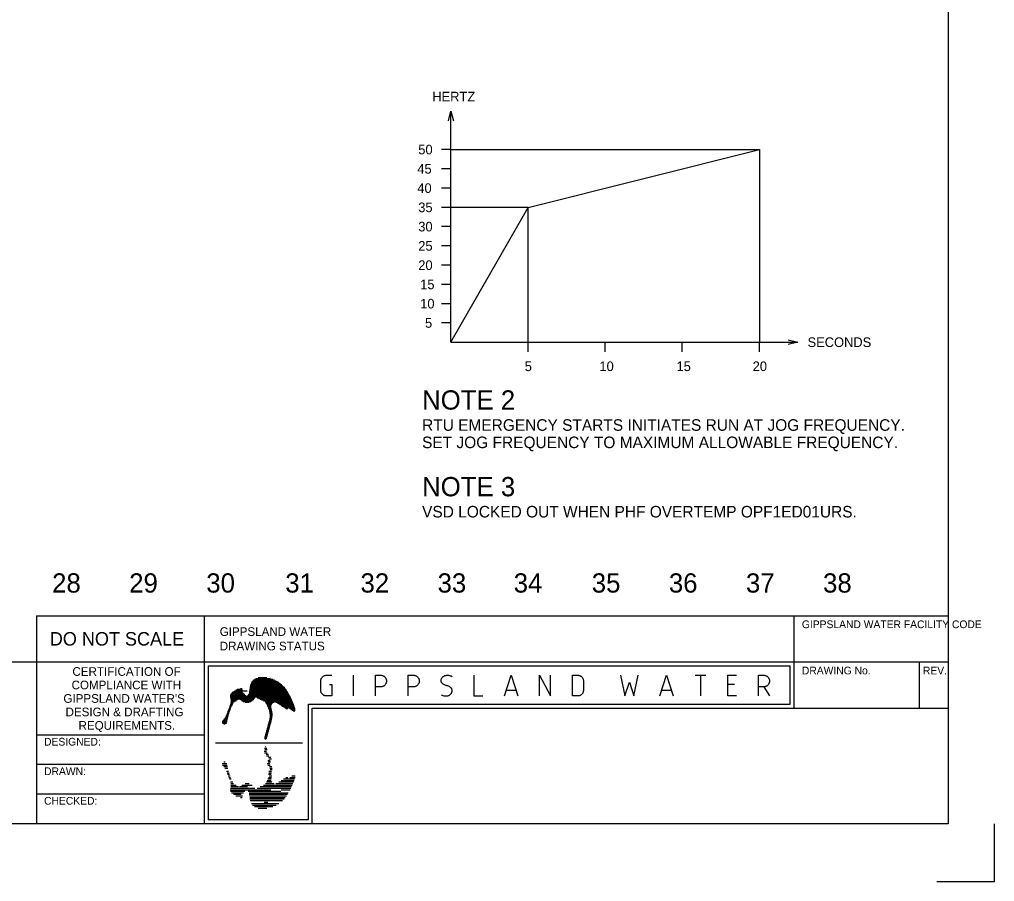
# Model space of a CAD drawing. Extents: x 0 to 841, y 0 to 594.
# Drawn here: x 588.1 to 841, y 0 to 223.8 of the extents above; entities that cross this region are included whole.
import ezdxf

# ---------------------------------------------------------------- set-up
doc = ezdxf.new("R2010")
doc.units = 0
doc.layers.add('A1BORDER', color=7, linetype='Continuous')
doc.layers.add('Level 1', color=7, linetype='Continuous')

msp = doc.modelspace()

# ---------------------------------------------------------------- linework, layer by layer
at = {"layer": 'A1BORDER'}
for p, q in [((829, 581), (829, 15)), ((592.5, 69), (592.5, 15)), ((592.5, 69), (829, 69)), ((636, 69), (636, 15)), ((789, 45), (789, 69)), ((28, 57), (829, 57)), ((637, 56), (788, 56)), ((637, 56), (637, 16)), ((788, 46), (788, 56)), ((821.5, 45), (821.5, 57)), ((647.88, 50.72), (656.5, 50.72)), ((647.91, 50.92), (656.3, 50.92)), ((647.96, 51.12), (656.08, 51.12)), ((648.03, 51.32), (655.85, 51.32)), ((648.12, 51.52), (655.59, 51.52)), ((648.23, 51.72), (655.31, 51.72)), ((648.37, 51.92), (655, 51.92)), ((648.53, 52.12), (654.64, 52.12)), ((648.74, 52.32), (654.24, 52.32)), ((649.02, 52.52), (653.76, 52.52)), ((649.39, 52.72), (653.15, 52.72)), ((650.01, 52.92), (652.2, 52.92)), ((642.73, 48.12), (658.25, 48.12)), ((642.75, 48.32), (646.79, 48.32)), ((642.81, 48.52), (646.55, 48.52)), ((642.9, 48.72), (646.37, 48.72)), ((643.04, 48.92), (646.16, 48.92)), ((643.26, 49.12), (645.9, 49.12)), ((643.54, 49.32), (645.57, 49.32)), ((643.85, 49.52), (647.09, 49.52)), ((644.18, 49.72), (645.89, 49.72)), ((644.54, 49.92), (645.36, 49.92)), ((645.37, 50.12), (645.86, 50.12)), ((647.19, 48.32), (658.14, 48.32)), ((647.42, 48.52), (658.03, 48.52)), ((647.54, 48.72), (657.92, 48.72)), ((647.61, 48.92), (657.8, 48.92)), ((647.63, 49.12), (657.68, 49.12)), ((647.66, 49.32), (657.57, 49.32)), ((647.69, 49.52), (657.44, 49.52)), ((647.71, 49.72), (657.31, 49.72)), ((647.75, 49.92), (657.17, 49.92)), ((647.78, 50.12), (657.02, 50.12)), ((647.81, 50.32), (656.86, 50.32)), ((647.85, 50.52), (656.69, 50.52)), ((642.65, 45.72), (643.2, 45.72)), ((642.72, 45.92), (643.3, 45.92)), ((642.74, 47.92), (658.35, 47.92)), ((642.79, 47.72), (649.08, 47.72)), ((642.79, 46.12), (643.4, 46.12)), ((642.83, 47.52), (648.95, 47.52)), ((642.84, 46.32), (643.5, 46.32)), ((642.85, 47.31), (644.88, 47.31)), ((642.87, 47.12), (644.57, 47.12)), ((642.87, 46.52), (643.6, 46.52)), ((642.88, 46.92), (644.23, 46.92)), ((642.88, 46.72), (643.83, 46.72)), ((645.14, 47.31), (648.83, 47.31)), ((645.49, 47.12), (648.67, 47.12)), ((645.76, 46.92), (648.42, 46.92)), ((646.05, 46.72), (648.11, 46.72)), ((646.62, 46.52), (647.67, 46.52)), ((649.72, 47.72), (658.45, 47.72)), ((650.12, 47.52), (658.55, 47.52)), ((650.48, 47.31), (658.64, 47.31)), ((650.87, 47.12), (658.73, 47.12)), ((651.36, 46.92), (658.82, 46.92)), ((651.76, 46.72), (658.9, 46.72)), ((651.88, 46.52), (654.15, 46.52)), ((651.99, 46.32), (653.71, 46.32)), ((652.1, 46.12), (653.52, 46.12)), ((652.2, 45.92), (653.4, 45.92)), ((652.31, 45.72), (653.33, 45.72)), ((654.57, 46.52), (658.99, 46.52)), ((655, 46.32), (659.07, 46.32)), ((655.31, 46.12), (659.14, 46.12)), ((655.62, 45.92), (659.22, 45.92)), ((655.93, 45.72), (659.29, 45.72)), ((663, 46), (788, 46)), ((663, 16), (663, 46)), ((641.64, 43.12), (642.25, 43.12)), ((641.73, 43.32), (642.3, 43.32)), ((641.82, 43.51), (642.35, 43.51)), ((641.91, 43.72), (642.41, 43.72)), ((641.99, 43.92), (642.48, 43.92)), ((642.06, 44.12), (642.55, 44.12)), ((642.13, 44.32), (642.62, 44.32)), ((642.21, 44.52), (642.69, 44.52)), ((642.28, 44.72), (642.76, 44.72)), ((642.35, 44.92), (642.83, 44.92)), ((642.43, 45.12), (642.9, 45.12)), ((642.5, 45.32), (643, 45.32)), ((642.57, 45.52), (643.1, 45.52)), ((652.41, 45.52), (653.31, 45.52)), ((652.5, 45.32), (653.34, 45.32)), ((652.6, 45.12), (653.38, 45.12)), ((652.69, 44.92), (653.41, 44.92)), ((652.78, 44.72), (653.44, 44.72)), ((652.83, 44.52), (653.48, 44.52)), ((652.86, 44.32), (653.53, 44.32)), ((652.89, 44.12), (653.57, 44.12)), ((652.91, 43.92), (653.62, 43.92)), ((652.94, 43.72), (653.67, 43.72)), ((652.97, 43.51), (653.71, 43.51)), ((653, 43.32), (653.69, 43.32)), ((653.02, 43.12), (653.67, 43.12)), ((656.24, 45.52), (659.35, 45.52)), ((656.55, 45.32), (659.42, 45.32)), ((656.86, 45.12), (657.74, 45.12)), ((657.17, 44.92), (657.68, 44.92)), ((657.51, 44.72), (657.54, 44.72)), ((657.91, 45.12), (659.48, 45.12)), ((658.19, 44.92), (659.54, 44.92)), ((658.47, 44.72), (659.59, 44.72)), ((658.75, 44.52), (659.58, 44.52)), ((659.02, 44.32), (659.47, 44.32)), ((664, 45), (829, 45)), ((664, 15), (664, 45)), ((640.62, 41.32), (641.88, 41.32)), ((640.63, 41.52), (641.93, 41.52)), ((640.72, 41.12), (641.73, 41.12)), ((640.73, 41.72), (641.95, 41.72)), ((640.9, 41.92), (641.97, 41.92)), ((641.03, 40.92), (641.43, 40.92)), ((641.1, 42.12), (642, 42.12)), ((641.25, 42.31), (642.04, 42.31)), ((641.37, 42.52), (642.09, 42.52)), ((641.46, 42.72), (642.15, 42.72)), ((641.55, 42.92), (642.2, 42.92)), ((652.47, 40.52), (653.1, 40.52)), ((652.52, 40.72), (653.15, 40.72)), ((652.57, 40.92), (653.2, 40.92)), ((652.63, 41.12), (653.26, 41.12)), ((652.68, 41.32), (653.31, 41.32)), ((652.74, 41.52), (653.37, 41.52)), ((652.79, 41.72), (653.41, 41.72)), ((652.85, 41.92), (653.45, 41.92)), ((652.9, 42.12), (653.49, 42.12)), ((652.95, 42.31), (653.53, 42.31)), ((652.99, 42.52), (653.57, 42.52)), ((653.03, 42.72), (653.61, 42.72)), ((653.05, 42.92), (653.64, 42.92)), ((636, 38), (592.5, 38)), ((651.82, 38.12), (652.44, 38.12)), ((651.87, 38.32), (652.5, 38.32)), ((651.92, 38.52), (652.55, 38.52)), ((651.98, 38.72), (652.61, 38.72)), ((652.03, 38.92), (652.66, 38.92)), ((652.09, 39.12), (652.72, 39.12)), ((652.14, 39.32), (652.77, 39.32)), ((652.2, 39.52), (652.82, 39.52)), ((652.25, 39.72), (652.88, 39.72)), ((652.3, 39.92), (652.93, 39.92)), ((652.36, 40.12), (652.99, 40.12)), ((652.41, 40.32), (653.04, 40.32)), ((638.93, 35.98), (661.47, 35.98)), ((651.63, 37.32), (652.23, 37.32)), ((651.64, 37.12), (652.17, 37.12)), ((651.65, 37.52), (652.28, 37.52)), ((651.71, 37.72), (652.34, 37.72)), ((651.76, 37.92), (652.39, 37.92)), ((651.79, 36.92), (651.9, 36.92)), ((651.54, 33.84), (652.17, 33.84)), ((651.63, 34.64), (652.23, 34.64)), ((651.65, 33.44), (652.28, 33.44)), ((651.71, 34.24), (652.34, 34.24)), ((651.79, 35.04), (651.9, 35.04)), ((652.03, 33.04), (652.66, 33.04)), ((640.62, 30.64), (641.88, 30.64)), ((641.03, 31.04), (641.43, 31.04)), ((652.14, 32.64), (652.77, 32.64)), ((652.34, 30.64), (652.97, 30.64)), ((652.47, 31.44), (653.1, 31.44)), ((652.57, 31.04), (653.2, 31.04)), ((652.66, 32.24), (653.29, 32.24)), ((652.77, 31.84), (653.4, 31.84)), ((636, 30.34), (592.5, 30.34)), ((640.73, 30.24), (641.95, 30.24)), ((641.1, 29.84), (642, 29.84)), ((641.37, 29.44), (642.09, 29.44)), ((641.73, 28.64), (642.3, 28.64)), ((641.91, 28.24), (642.41, 28.24)), ((642.06, 27.84), (642.55, 27.84)), ((652.45, 30.24), (653.07, 30.24)), ((652.66, 27.84), (653.35, 27.84)), ((652.72, 28.24), (653.44, 28.24)), ((652.77, 28.64), (653.46, 28.64)), ((652.9, 29.84), (653.49, 29.84)), ((652.99, 29.44), (653.57, 29.44)), ((653.05, 29.04), (653.64, 29.04)), ((642.21, 27.44), (642.69, 27.44)), ((642.35, 27.04), (642.83, 27.04)), ((642.5, 26.64), (643, 26.64)), ((642.79, 25.84), (643.4, 25.84)), ((642.87, 25.44), (643.6, 25.44)), ((646.62, 25.44), (647.67, 25.44)), ((651.88, 25.44), (654.15, 25.44)), ((652.1, 25.84), (653.52, 25.84)), ((652.31, 26.24), (653.33, 26.24)), ((652.5, 26.64), (653.34, 26.64)), ((652.69, 27.04), (653.41, 27.04)), ((652.83, 27.44), (653.48, 27.44)), ((654.57, 25.44), (658.99, 25.44)), ((655.31, 25.84), (659.14, 25.84)), ((655.93, 26.24), (659.29, 26.24)), ((656.55, 26.64), (659.42, 26.64)), ((657.17, 27.04), (657.68, 27.04)), ((658.19, 27.04), (659.54, 27.04)), ((658.75, 27.44), (659.58, 27.44)), ((642.73, 23.84), (653.27, 23.84)), ((642.79, 24.24), (649.08, 24.24)), ((642.81, 23.44), (646.55, 23.44)), ((642.85, 24.65), (644.88, 24.65)), ((642.88, 25.04), (644.23, 25.04)), ((643.04, 23.04), (646.16, 23.04)), ((645.14, 24.65), (647.18, 24.65)), ((645.76, 25.04), (648.42, 25.04)), ((647.42, 23.44), (655.89, 23.44)), ((647.61, 23.04), (657.8, 23.04)), ((649.72, 24.24), (658.45, 24.24)), ((650.48, 24.65), (658.64, 24.65)), ((651.36, 25.04), (658.82, 25.04)), ((655.94, 23.84), (658.25, 23.84)), ((636, 22.67), (592.5, 22.67)), ((643.54, 22.64), (645.57, 22.64)), ((644.18, 22.24), (645.89, 22.24)), ((645.37, 21.84), (645.86, 21.84)), ((647.66, 22.64), (657.57, 22.64)), ((647.71, 22.24), (657.31, 22.24)), ((647.78, 21.84), (657.02, 21.84)), ((647.85, 21.44), (656.69, 21.44)), ((647.91, 21.04), (656.3, 21.04)), ((648.23, 20.24), (655.31, 20.24)), ((651.57, 20.64), (652.44, 20.64)), ((648.53, 19.84), (654.64, 19.84)), ((649.02, 19.44), (653.76, 19.44)), ((650.01, 19.04), (652.2, 19.04)), ((663, 16), (637, 16)), ((829, 15), (28, 15)), ((829, 15), (829, 15)), ((841, 0), (841, 15)), ((826, 0), (841, 0))]:
    msp.add_line(p, q, dxfattribs=at)
for points in [[(668.49, 51.15), (669.06, 51.15), (669.06, 48.16), (667.64, 48.16), (667.51, 48.16), (667.39, 48.18), (667.28, 48.21), (667.15, 48.25), (667.04, 48.3), (666.93, 48.36), (666.82, 48.43), (666.73, 48.51), (666.64, 48.6), (666.55, 48.7), (666.48, 48.8), (666.41, 48.91), (666.35, 49.02), (666.31, 49.14), (666.27, 49.27), (666.24, 49.39), (666.22, 49.52), (666.22, 49.66), (666.22, 52.05), (666.22, 52.18), (666.24, 52.31), (666.27, 52.43), (666.31, 52.56), (666.35, 52.67), (666.41, 52.79), (666.48, 52.9), (666.55, 53), (666.64, 53.1), (666.73, 53.19), (666.82, 53.27), (666.93, 53.34), (667.04, 53.4), (667.15, 53.45), (667.28, 53.49), (667.39, 53.52), (667.51, 53.54), (667.64, 53.54), (669.06, 53.54)], [(674.74, 48.16), (674.74, 53.54)], [(680.42, 48.16), (680.42, 53.54), (681.84, 53.54), (681.96, 53.54), (682.08, 53.52), (682.2, 53.49), (682.32, 53.45), (682.43, 53.4), (682.54, 53.34), (682.65, 53.27), (682.74, 53.19), (682.84, 53.1), (682.92, 53), (682.99, 52.9), (683.06, 52.79), (683.12, 52.67), (683.17, 52.56), (683.21, 52.43), (683.23, 52.31), (683.25, 52.18), (683.26, 52.05), (683.25, 51.91), (683.23, 51.78), (683.21, 51.66), (683.17, 51.53), (683.12, 51.42), (683.06, 51.3), (682.99, 51.19), (682.92, 51.09), (682.84, 50.99), (682.74, 50.9), (682.65, 50.82), (682.54, 50.75), (682.43, 50.69), (682.32, 50.64), (682.2, 50.6), (682.08, 50.57), (681.96, 50.55), (681.84, 50.55), (680.42, 50.55)], [(688.93, 48.16), (688.93, 53.54), (690.35, 53.54), (690.47, 53.54), (690.59, 53.52), (690.71, 53.49), (690.83, 53.45), (690.94, 53.4), (691.05, 53.34), (691.16, 53.27), (691.26, 53.19), (691.35, 53.1), (691.43, 53), (691.51, 52.9), (691.57, 52.79), (691.63, 52.67), (691.68, 52.56), (691.72, 52.43), (691.75, 52.31), (691.76, 52.18), (691.77, 52.05), (691.76, 51.91), (691.75, 51.78), (691.72, 51.66), (691.68, 51.53), (691.63, 51.42), (691.57, 51.3), (691.51, 51.19), (691.43, 51.09), (691.35, 50.99), (691.26, 50.9), (691.16, 50.82), (691.05, 50.75), (690.94, 50.69), (690.83, 50.64), (690.71, 50.6), (690.59, 50.57), (690.47, 50.55), (690.35, 50.55), (688.93, 50.55)], [(697.45, 48.46), (697.67, 48.36), (697.9, 48.27), (698.12, 48.21), (698.36, 48.17), (698.6, 48.16), (698.84, 48.16), (698.87, 48.16), (699.03, 48.18), (699.18, 48.21), (699.33, 48.26), (699.48, 48.32), (699.62, 48.4), (699.72, 48.46), (699.81, 48.53), (699.9, 48.61), (699.98, 48.69), (700.05, 48.78), (700.11, 48.88), (700.17, 48.99), (700.22, 49.09), (700.25, 49.21), (700.28, 49.32), (700.29, 49.36), (700.3, 49.44), (700.3, 49.52), (700.3, 49.61), (700.29, 49.69), (700.27, 49.77), (700.25, 49.86), (700.22, 49.93), (700.18, 50.01), (700.14, 50.09), (700.09, 50.15), (700.04, 50.21), (700.01, 50.25), (699.85, 50.39), (699.69, 50.51), (699.52, 50.61), (699.34, 50.7), (699.15, 50.78), (698.95, 50.83), (698.87, 50.85), (698.68, 50.9), (698.49, 50.96), (698.3, 51.04), (698.12, 51.14), (697.96, 51.26), (697.8, 51.39), (697.73, 51.45), (697.67, 51.51), (697.62, 51.57), (697.58, 51.64), (697.53, 51.71), (697.5, 51.79), (697.47, 51.87), (697.46, 51.95), (697.44, 52.04), (697.43, 52.12), (697.43, 52.21), (697.44, 52.29), (697.45, 52.35), (697.47, 52.46), (697.51, 52.58), (697.55, 52.69), (697.61, 52.79), (697.67, 52.89), (697.74, 52.99), (697.82, 53.07), (697.9, 53.15), (697.99, 53.23), (698.02, 53.24), (698.15, 53.33), (698.3, 53.4), (698.44, 53.45), (698.6, 53.5), (698.75, 53.52), (698.87, 53.54), (699.11, 53.55), (699.35, 53.53), (699.58, 53.49), (699.82, 53.43), (700.04, 53.35), (700.27, 53.25)], [(705.96, 53.54), (705.96, 48.16), (708.23, 48.16)], [(713.91, 48.16), (715.61, 53.54), (717.32, 48.16)], [(722.99, 48.16), (722.99, 53.54), (725.83, 48.16), (725.83, 53.54)], [(731.52, 48.16), (731.52, 53.54), (732.94, 53.54), (733.06, 53.54), (733.18, 53.52), (733.3, 53.49), (733.42, 53.45), (733.53, 53.4), (733.64, 53.34), (733.75, 53.27), (733.84, 53.19), (733.94, 53.1), (734.02, 53), (734.09, 52.9), (734.16, 52.79), (734.22, 52.67), (734.27, 52.56), (734.31, 52.43), (734.33, 52.31), (734.35, 52.18), (734.36, 52.05), (734.36, 49.66), (734.35, 49.52), (734.33, 49.39), (734.31, 49.27), (734.27, 49.14), (734.22, 49.02), (734.16, 48.91), (734.09, 48.8), (734.02, 48.7), (733.94, 48.6), (733.84, 48.51), (733.75, 48.43), (733.64, 48.36), (733.53, 48.3), (733.42, 48.25), (733.3, 48.21), (733.18, 48.18), (733.06, 48.16), (732.94, 48.16), (731.52, 48.16)], [(744.01, 53.54), (745.14, 48.16), (746.28, 51.75), (747.41, 48.16), (748.55, 53.54)], [(754.22, 48.16), (755.92, 53.54), (757.63, 48.16)], [(763.31, 53.54), (766.15, 53.54)], [(764.73, 53.54), (764.73, 48.16)], [(774.09, 48.16), (771.82, 48.16), (771.82, 53.54), (774.09, 53.54)], [(779.78, 48.16), (779.78, 53.54), (781.2, 53.54), (781.32, 53.54), (781.44, 53.52), (781.56, 53.49), (781.68, 53.45), (781.79, 53.4), (781.9, 53.34), (782.01, 53.27), (782.1, 53.19), (782.2, 53.1), (782.28, 53), (782.35, 52.9), (782.42, 52.79), (782.48, 52.67), (782.53, 52.56), (782.56, 52.43), (782.59, 52.31), (782.61, 52.18), (782.61, 52.05), (782.61, 51.91), (782.59, 51.78), (782.56, 51.66), (782.53, 51.53), (782.48, 51.42), (782.42, 51.3), (782.35, 51.19), (782.28, 51.09), (782.2, 50.99), (782.1, 50.9), (782.01, 50.82), (781.9, 50.75), (781.79, 50.69), (781.68, 50.64), (781.56, 50.6), (781.44, 50.57), (781.32, 50.55), (781.2, 50.55), (779.78, 50.55)], [(773.53, 51.15), (771.82, 51.15)], [(714.48, 49.66), (716.75, 49.66)], [(754.79, 49.66), (757.06, 49.66)], [(781.2, 50.55), (782.61, 48.16)]]:
    msp.add_lwpolyline(points, dxfattribs=at)
at = {"layer": 'Level 1'}
for p, q in [((700, 140), (700, 200)), ((700, 190), (697.5, 190)), ((700, 190), (780, 190)), ((720, 175), (780, 190)), ((780, 190), (780, 140)), ((700, 185), (697.5, 185)), ((700, 180), (697.5, 180)), ((700, 175), (697.5, 175)), ((700, 140), (720, 175)), ((720, 175), (700, 175)), ((720, 140), (720, 175)), ((700, 170), (697.5, 170)), ((700, 165), (697.5, 165)), ((700, 160), (697.5, 160)), ((700, 155), (697.5, 155)), ((700, 150), (697.5, 150)), ((700, 145), (697.5, 145)), ((700, 140), (790, 140)), ((720, 137.5), (720, 140)), ((740, 137.5), (740, 140)), ((760, 137.5), (760, 140)), ((780, 137.5), (780, 140))]:
    msp.add_line(p, q, dxfattribs=at)
for points in [[(699.38, 197.5), (700, 200), (700.62, 197.5)], [(787.5, 140.62), (790, 140), (787.5, 139.38)]]:
    msp.add_lwpolyline(points, dxfattribs=at)

# ---------------------------------------------------------------- texts
at = {"layer": 'A1BORDER'}
for s, height, p in [('GIPPSLAND WATER', 2.25, (640, 63.75)), ('GIPPSLAND WATER FACILITY CODE', 2, (791.03, 65.77)), ('DO NOT SCALE', 3.5, (595.92, 61.25)), ('DRAWING STATUS', 2.25, (640, 60)), ('CERTIFICATION OF', 2.25, (601.79, 53.39)), ('DRAWING No.', 2, (791.03, 53.77)), ('REV.', 2, (822.43, 53.77)), ('COMPLIANCE WITH', 2.25, (601.57, 49.89)), ("GIPPSLAND WATER'S", 2.25, (599.45, 46.39)), ('DESIGN & DRAFTING', 2.25, (600, 42.89)), ('REQUIREMENTS.', 2.25, (603.37, 39.39)), ('DESIGNED:', 2, (594.44, 35.29)), ('DRAWN:', 2, (594.44, 27.62)), ('CHECKED:', 2, (594.44, 19.95))]:
    msp.add_text(s, height=height, dxfattribs=at).set_placement(p)
at = {"layer": 'Level 1'}
for s, height, p in [('HERTZ', 2.5, (695.14, 202.5)), ('50', 2.5, (691.51, 188.75)), ('45', 2.5, (691.26, 183.75)), ('40', 2.5, (691.26, 178.75)), ('35', 2.5, (691.51, 173.75)), ('30', 2.5, (691.51, 168.75)), ('25', 2.5, (691.51, 163.75)), ('20', 2.5, (691.51, 158.75)), ('15', 2.5, (692.01, 153.75)), ('10', 2.5, (692.01, 148.75)), ('5', 2.5, (693.26, 143.75)), ('SECONDS', 2.5, (792.5, 138.75)), ('5', 2.5, (719.13, 132.5)), ('10', 2.5, (738.51, 132.5)), ('15', 2.5, (758.51, 132.5)), ('20', 2.5, (778.26, 132.5)), ('NOTE 2', 5, (692.5, 122.5)), ('RTU EMERGENCY STARTS INITIATES RUN AT JOG FREQUENCY.', 3, (692.5, 117)), ('SET JOG FREQUENCY TO MAXIMUM ALLOWABLE FREQUENCY.', 3, (692.5, 112.5)), ('NOTE 3', 5, (692.5, 100)), ('VSD LOCKED OUT WHEN PHF OVERTEMP OPF1ED01URS.', 3, (692.5, 94.5)), ('28', 5, (596.52, 75)), ('29', 5, (616.52, 75)), ('30', 5, (636.52, 75)), ('31', 5, (657.01, 75)), ('32', 5, (676.52, 75)), ('33', 5, (696.52, 75)), ('34', 5, (716.27, 75)), ('35', 5, (736.52, 75)), ('36', 5, (756.52, 75)), ('37', 5, (776.52, 75)), ('38', 5, (796.52, 75))]:
    msp.add_text(s, height=height, dxfattribs=at).set_placement(p)

doc.saveas('drawing.dxf')
